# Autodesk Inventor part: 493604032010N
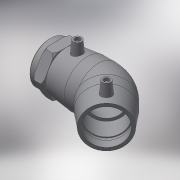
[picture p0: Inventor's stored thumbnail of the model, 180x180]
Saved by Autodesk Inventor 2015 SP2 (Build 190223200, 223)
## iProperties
Created: 2017-06
Part Number: 493604032010N
Material: Generic
Description: PLASSON 45° ELBOW TRANSITION FEMALE 32-1"
Document SubType Name: Modeling
Designer: KIM
Mass: 121.909 g
Surface Area: 403.853 cm^2
Volume: 121.909 cm^3
Density: 1 g/cm^3
Appearance: Default
Author: KIM
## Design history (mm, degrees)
derived "493604.ipt"
feature "Solid1::493604.ipt"
tag "TaggingFeature1"
body "Solid1"
other parameters: "d2" = 44, "d4" = 25.25, "d5" = 39.6, "d8" = 168 deg, "d10" = 17.6, "d11" = 5.86667, "d29" = 42, "d30" = 15, "d31" = 35.35, "d34" = 5 deg, "d41" = 4, "d42" = 14, "d43" = 0, "d49" = 32, "d50" = 27.2, "d51" = 17.6, "d52" = 44, "d54" = 135 deg, "d86" = 19.8, "d87" = 135 deg, "d88" = 101, "d90" = 44, "d91" = 0, "d92" = 44, "d93" = 0, "d101" = 3, "d102" = 0, "d107" = 0.1, "d108" = 27, "d112" = 44.88, "d113" = 30.291, "d114" = 36, "d128" = 12, "d129" = 0, "d132" = 1.6, "d133" = 45 deg, "d134" = 45 deg, "d136" = 0.96, "d_" = 32, "L_" = 141, "L_1" = 44, "D_" = 27, "A_" = 42, "d_2" = 12, "Rp_" = 30.291, "D_1" = 44
